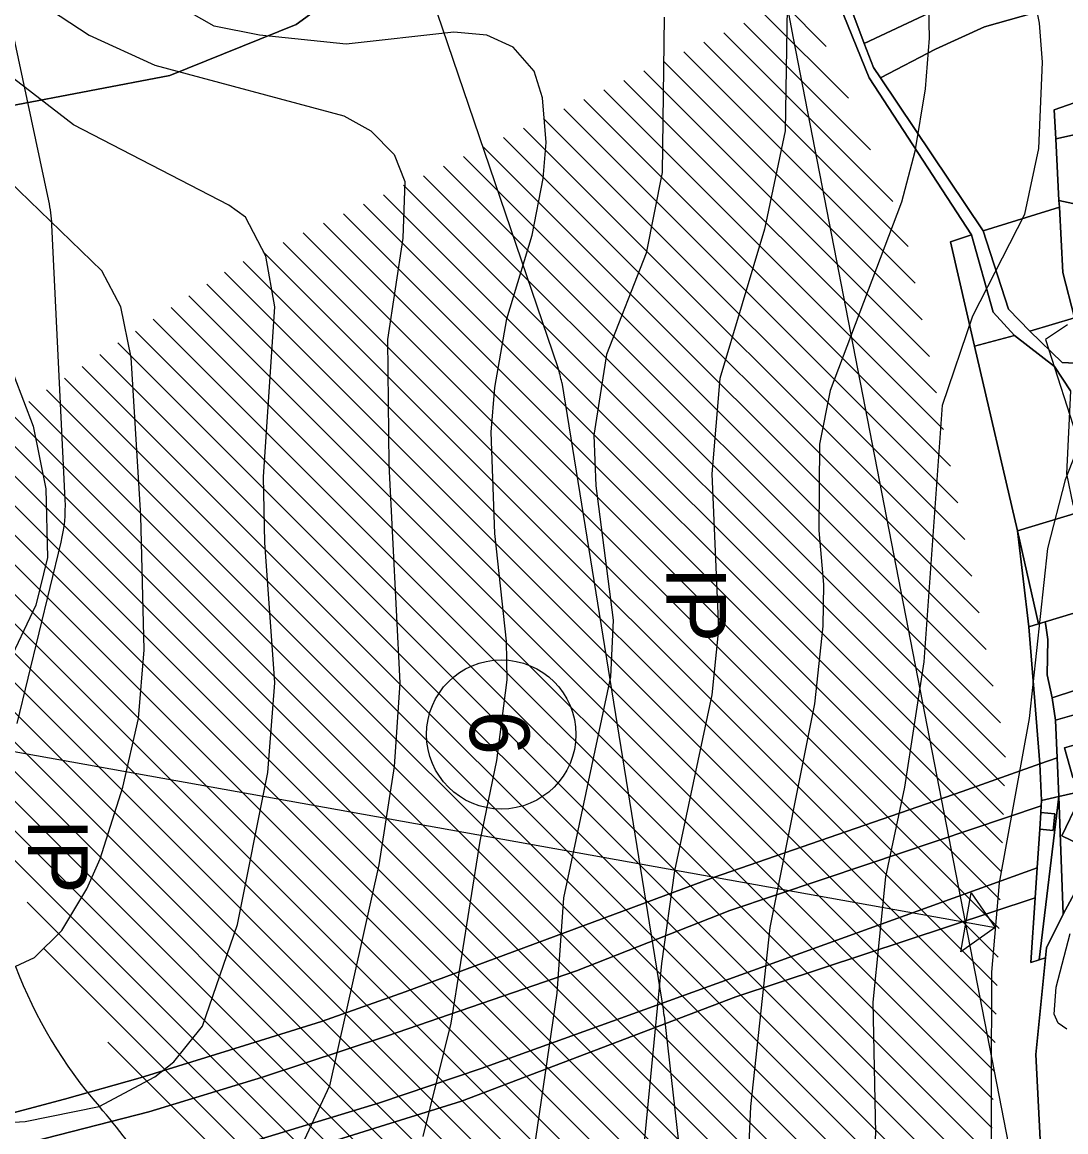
# Model space of a CAD drawing. Extents: x -510989 to -501240, y -1184665 to -1176098.
# Drawn here: x -509912.8 to -509563.3, y -1179809.4 to -1179437.6 of the extents above; entities that cross this region are included whole.
import ezdxf

# ---------------------------------------------------------------- set-up
doc = ezdxf.new("R2010")
doc.units = 0
for name, color, linetype in [('NAVRH_interakcni_prvky', 7, 'Continuous'), ('NAVRH_rozvodnice', 7, 'Continuous'), ('orna_puda', 7, 'Continuous'), ('ostatni_plocha_x_ostatni_komunikace', 7, 'Continuous'), ('ostatni_plocha_x_silnice', 7, 'Continuous'), ('ovocny_sad', 7, 'Continuous'), ('STAV_erozne_ohrozene_plochy', 7, 'Continuous'), ('STAV_odtokove_linie', 7, 'Continuous'), ('STAV_systematicke_odvodneni', 7, 'Continuous'), ('trvaly_travni_porost', 7, 'Continuous'), ('vrstevnice_01', 7, 'Continuous'), ('vrstevnice_02', 7, 'Continuous'), ('zahrada', 7, 'Continuous'), ('zastavena_plocha_a_nadvori', 7, 'Continuous')]:
    doc.layers.add(name, color=color, linetype=linetype)

msp = doc.modelspace()

# ---------------------------------------------------------------- linework, layer by layer
at = {"layer": 'NAVRH_interakcni_prvky'}
for p, q in [((-509791.67, -1179382.12), (-509733.43, -1179553.31)), ((-509903.92, -1179497.53), (-509919.26, -1179425.52)), ((-509898.44, -1179597.66), (-509902.88, -1179505.54)), ((-509732.15, -1179558.39), (-509698.04, -1179769.18)), ((-509914.54, -1179672.6), (-509899.79, -1179611.87)), ((-509697.84, -1179770.62), (-509679.58, -1179932.59))]:
    msp.add_line(p, q, dxfattribs=at)
for centre, start, end in [((-509952.82, -1179507.95), 2.7587, 12.0311), ((-509948.38, -1179600.07), 346.3496, 2.7587)]:
    msp.add_arc(centre, 50, start, end, dxfattribs=at)
for centre, start_param, end_param in [((-509813.59, -1179563.13), 0.096839, 0.201455), ((-509779.47, -1179773.93), 0.067567, 0.096839)]:
    msp.add_ellipse(centre, major_axis=(81.82, 0), ratio=0.600245, start_param=start_param, end_param=end_param, dxfattribs=at)
at = {"layer": 'NAVRH_rozvodnice'}
for centre, radius, start, end in [((-509769.66, -1179698.97), 155.49, 200.7272, 221.0092), ((-510050.65, -1179943.3), 216.87, 25.7756, 41.0092)]:
    msp.add_arc(centre, radius, start, end, dxfattribs=at)
at = {"layer": 'orna_puda'}
for points in [[(-509646.38, -1179413.87), (-509629.15, -1179456.33), (-509594.88, -1179508.89), (-509601.99, -1179511.21), (-509593.87, -1179546.25), (-509579.56, -1179608.03), (-509575.69, -1179640.23), (-509571.98, -1179686.17), (-509598.04, -1179695.37), (-509681.32, -1179724.23), (-509784.58, -1179762.55), (-509812.55, -1179772.46), (-509843.4, -1179782.08), (-509873.28, -1179791.41), (-509898.66, -1179798.48), (-509924.84, -1179805.39)], [(-510233.91, -1179517.72), (-510085.19, -1179504.1), (-510066.77, -1179500.85), (-510030.15, -1179490.83), (-510002.08, -1179487.1), (-509960.82, -1179477.55), (-509917.23, -1179465.75), (-509863.35, -1179455.49), (-509821.13, -1179438.42), (-509807.97, -1179428.77)], [(-509913.51, -1179813.75), (-509870.46, -1179802.75), (-509832.41, -1179791.08), (-509790.88, -1179777.39), (-509727.17, -1179755.55), (-509675.85, -1179735.34), (-509630, -1179719.89), (-509571.56, -1179700.19), (-509571.71, -1179702.48), (-509572.08, -1179708.08), (-509572.93, -1179721), (-509712.37, -1179771.32), (-509759.16, -1179788.2), (-509793.14, -1179799.75), (-509845.95, -1179815.81), (-509867.41, -1179823.72), (-509900.03, -1179832.04), (-509926.9, -1179837.49)], [(-509934.38, -1179847.85), (-509867.17, -1179830.91), (-509792.97, -1179807.66), (-509765.76, -1179799.13), (-509673.8, -1179764.23), (-509573.59, -1179731.06), (-509575.02, -1179752.72), (-509572.29, -1179751.86), (-509570.13, -1179751.18), (-509573.4, -1179783.55), (-509570.8, -1179833.9), (-509608.19, -1179847.61), (-509606.53, -1179883.25), (-509569.24, -1179868.59), (-509568.53, -1179892.94), (-509568.33, -1179899.97), (-509592.74, -1179908.1), (-509696.74, -1179942.74), (-509799.96, -1179976.4), (-509904.89, -1180011.19), (-509945.61, -1180021.74)]]:
    msp.add_lwpolyline(points, dxfattribs=at)
for points in [[(-509591.02, -1179507.59), (-509565.49, -1179499.64), (-509564.32, -1179521.49), (-509560.38, -1179536.66), (-509575.36, -1179541.18), (-509582.47, -1179533.78)], [(-509601.99, -1179511.21), (-509594.88, -1179508.89), (-509587.67, -1179534.77), (-509580.5, -1179542.59), (-509593.87, -1179546.25)], [(-509560.38, -1179536.66), (-509557.74, -1179545.16), (-509558.3, -1179552.05), (-509564.49, -1179551.71), (-509575.36, -1179541.18)], [(-509593.87, -1179546.25), (-509580.5, -1179542.59), (-509567.12, -1179553.04), (-509561.77, -1179561.13), (-509563.04, -1179588.93), (-509560.96, -1179599.22), (-509559.14, -1179601.9), (-509579.56, -1179608.03)], [(-509559.14, -1179601.9), (-509556.78, -1179605.36), (-509554.87, -1179614.83), (-509550.33, -1179622.85), (-509549.98, -1179627.33), (-509548.87, -1179632.92), (-509552.15, -1179633.05), (-509570.24, -1179638.57), (-509572.45, -1179639.24), (-509579.56, -1179608.03)], [(-509579.56, -1179608.03), (-509572.45, -1179639.24), (-509575.69, -1179640.23)], [(-509572.45, -1179639.24), (-509570.24, -1179638.57), (-509570.06, -1179639.82), (-509569.38, -1179644.52), (-509569.6, -1179656.29), (-509567.86, -1179664.07), (-509566.73, -1179671.5), (-509566.2, -1179684.13), (-509571.98, -1179686.17), (-509575.69, -1179640.23)], [(-509566.73, -1179671.5), (-509546.47, -1179665.67), (-509544.4, -1179672.71), (-509543.55, -1179692.05), (-509565.65, -1179697.05), (-509566.2, -1179684.13)], [(-509552.85, -1179677.69), (-509563.82, -1179680.81), (-509561.01, -1179690.71), (-509550.13, -1179687.62), (-509550.88, -1179685), (-509549.45, -1179684.59), (-509550.59, -1179680.57), (-509551.93, -1179680.95)], [(-509571.98, -1179686.17), (-509571.44, -1179698.45), (-509571.56, -1179700.19), (-509630, -1179719.89), (-509675.85, -1179735.34), (-509727.17, -1179755.55), (-509790.88, -1179777.39), (-509832.41, -1179791.08), (-509870.46, -1179802.75), (-509913.51, -1179813.75), (-509949.76, -1179823.34), (-509961.4, -1179812.45), (-509946.76, -1179810.17), (-509924.84, -1179805.39), (-509898.66, -1179798.48), (-509873.28, -1179791.41), (-509843.4, -1179782.08), (-509812.55, -1179772.46), (-509784.58, -1179762.55), (-509681.32, -1179724.23), (-509598.04, -1179695.37)], [(-509566.2, -1179684.13), (-509565.65, -1179697.05), (-509571.44, -1179698.45), (-509571.98, -1179686.17)], [(-509571.44, -1179698.45), (-509565.65, -1179697.05), (-509572.29, -1179751.86), (-509575.02, -1179752.72), (-509573.59, -1179731.06), (-509572.93, -1179721), (-509572.08, -1179708.08), (-509567.51, -1179708.49), (-509567.01, -1179702.9), (-509571.71, -1179702.48), (-509571.56, -1179700.19)], [(-509565.65, -1179697.05), (-509564.2, -1179736.53), (-509569.79, -1179747.85), (-509570.13, -1179751.18), (-509572.29, -1179751.86)], [(-509573.59, -1179731.06), (-509673.8, -1179764.23), (-509765.76, -1179799.13), (-509792.97, -1179807.66), (-509867.17, -1179830.91), (-509934.38, -1179847.85), (-509942.51, -1179849.9), (-509966.28, -1179853.46), (-510002.2, -1179858.21), (-510043.39, -1179861.58), (-510096.1, -1179867.95), (-510116.32, -1179858.81), (-510092.18, -1179857.59), (-509971.29, -1179844.16), (-509953.77, -1179842.93), (-509926.9, -1179837.49), (-509900.03, -1179832.04), (-509867.41, -1179823.72), (-509845.95, -1179815.81), (-509793.14, -1179799.75), (-509759.16, -1179788.2), (-509712.37, -1179771.32), (-509572.93, -1179721)]]:
    msp.add_lwpolyline(points, close=True, dxfattribs=at)
at = {"layer": 'ostatni_plocha_x_ostatni_komunikace'}
for points in [[(-509561.77, -1179561.13), (-509567.12, -1179553.04), (-509580.5, -1179542.59), (-509587.67, -1179534.77), (-509594.88, -1179508.89), (-509629.15, -1179456.33), (-509646.38, -1179413.87)], [(-509635.67, -1179431.97), (-509630.81, -1179444.75), (-509627.75, -1179452.82), (-509625.39, -1179456.34), (-509591.02, -1179507.59), (-509582.47, -1179533.78), (-509575.36, -1179541.18), (-509564.49, -1179551.71), (-509558.3, -1179552.05)]]:
    msp.add_lwpolyline(points, dxfattribs=at)
at = {"layer": 'ostatni_plocha_x_silnice'}
msp.add_lwpolyline([(-509563.62, -1180023.92), (-509565.24, -1180006.24), (-509567.68, -1179922.21), (-509567.84, -1179916.75), (-509568.18, -1179905.23), (-509568.33, -1179899.97), (-509568.53, -1179892.94), (-509569.24, -1179868.59), (-509570.8, -1179833.9), (-509573.4, -1179783.55), (-509570.13, -1179751.18), (-509569.79, -1179747.85), (-509564.2, -1179736.53), (-509552.3, -1179714.42)], dxfattribs=at)
at = {"layer": 'ovocny_sad'}
msp.add_lwpolyline([(-509558.04, -1179429.89), (-509547.82, -1179460.78), (-509551.94, -1179461.65), (-509567.22, -1179467.05), (-509566.71, -1179476.72), (-509565.61, -1179497.44), (-509565.49, -1179499.64), (-509591.02, -1179507.59), (-509625.39, -1179456.34), (-509607.01, -1179446.64), (-509590.53, -1179439.22)], close=True, dxfattribs=at)
at = {"layer": 'STAV_erozne_ohrozene_plochy'}
for p, q in [((-509657.7, -1179431.63), (-509643.57, -1179445.76)), ((-509664.41, -1179434.82), (-509636.14, -1179463.09)), ((-509671.12, -1179438.01), (-509628.71, -1179480.42)), ((-509684.54, -1179444.39), (-509616.15, -1179512.78)), ((-509677.83, -1179441.2), (-509621.28, -1179497.75)), ((-509691.24, -1179447.58), (-509613.77, -1179525.05)), ((-509697.95, -1179450.78), (-509611.4, -1179537.33)), ((-509704.66, -1179453.97), (-509609.02, -1179549.61)), ((-509711.37, -1179457.16), (-509606.64, -1179561.88)), ((-509718.07, -1179460.35), (-509604.27, -1179574.16)), ((-509731.49, -1179466.73), (-509599.51, -1179598.71)), ((-509724.78, -1179463.54), (-509601.89, -1179586.44)), ((-509738.2, -1179469.93), (-509597.13, -1179610.99)), ((-509744.91, -1179473.12), (-509594.76, -1179623.27)), ((-509751.61, -1179476.31), (-509592.38, -1179635.54)), ((-509758.32, -1179479.5), (-509590, -1179647.82)), ((-509765.03, -1179482.69), (-509587.63, -1179660.1)), ((-509778.44, -1179489.08), (-509583.56, -1179683.96)), ((-509771.74, -1179485.88), (-509585.25, -1179672.37)), ((-509785.15, -1179492.27), (-509583.9, -1179693.52)), ((-509791.86, -1179495.46), (-509584.24, -1179703.08)), ((-509798.57, -1179498.65), (-509584.58, -1179712.64)), ((-509805.28, -1179501.84), (-509584.92, -1179722.19)), ((-509811.98, -1179505.03), (-509585.26, -1179731.75)), ((-509825.4, -1179511.42), (-509585.94, -1179750.87)), ((-509818.69, -1179508.23), (-509585.6, -1179741.31)), ((-509832.11, -1179514.61), (-509586.29, -1179760.43)), ((-509838.82, -1179517.8), (-509586.63, -1179769.99)), ((-509845.08, -1179521.43), (-509586.97, -1179779.55)), ((-509851.04, -1179525.37), (-509587.31, -1179789.11)), ((-509857, -1179529.31), (-509587.65, -1179798.67)), ((-509862.96, -1179533.25), (-509587.99, -1179808.23)), ((-509868.92, -1179537.2), (-509588.33, -1179817.78)), ((-509874.88, -1179541.14), (-509588.67, -1179827.34)), ((-509880.83, -1179545.08), (-509589.01, -1179836.9)), ((-509886.79, -1179549.02), (-509589.35, -1179846.46)), ((-509892.75, -1179552.96), (-509589.69, -1179856.02)), ((-509898.71, -1179556.9), (-509590.03, -1179865.58)), ((-509904.67, -1179560.84), (-509590.37, -1179875.14)), ((-509910.63, -1179564.78), (-509590.71, -1179884.7)), ((-509916.58, -1179568.73), (-509591.05, -1179894.26)), ((-509922.54, -1179572.67), (-509596.68, -1179898.52)), ((-509928.5, -1179576.61), (-509607.05, -1179898.06)), ((-509934.46, -1179580.55), (-509617.42, -1179897.59)), ((-509937.21, -1179587.7), (-509627.79, -1179897.12)), ((-509937.11, -1179597.69), (-509638.15, -1179896.65)), ((-509937.02, -1179607.69), (-509648.52, -1179896.18)), ((-509936.93, -1179617.68), (-509658.89, -1179895.72)), ((-509936.83, -1179627.67), (-509669.26, -1179895.25)), ((-509936.74, -1179637.66), (-509679.62, -1179894.78)), ((-509936.65, -1179647.66), (-509689.99, -1179894.31)), ((-509936.54, -1179657.66), (-509700.36, -1179893.84)), ((-509931.47, -1179672.63), (-509710.73, -1179893.38)), ((-509926.4, -1179687.6), (-509721.09, -1179892.91)), ((-509921.33, -1179702.57), (-509731.46, -1179892.44)), ((-509916.26, -1179717.54), (-509741.83, -1179891.97)), ((-509911.19, -1179732.51), (-509752.2, -1179891.5)), ((-509905.49, -1179748.11), (-509762.56, -1179891.04)), ((-509884.12, -1179779.38), (-509772.93, -1179890.57))]:
    msp.add_line(p, q, dxfattribs=at)
at = {"layer": 'STAV_odtokove_linie'}
msp.add_line((-509940.81, -1179677.5), (-509586.94, -1179741), dxfattribs=at)
msp.add_lwpolyline([(-509595.03, -1179729.41), (-509586.94, -1179741), (-509598.53, -1179749.1)], close=True, dxfattribs=at)
msp.add_circle((-509752.4, -1179676.3), 25, dxfattribs=at)
at = {"layer": 'STAV_systematicke_odvodneni'}
for p, q in [((-509680.24, -1179309.07), (-509654.64, -1179442.96)), ((-509654.64, -1179442.96), (-509576.02, -1179847.16))]:
    msp.add_line(p, q, dxfattribs=at)
at = {"layer": 'trvaly_travni_porost'}
msp.add_lwpolyline([(-509807.97, -1179428.77), (-509821.13, -1179438.42), (-509863.35, -1179455.49), (-509917.23, -1179465.75), (-509960.82, -1179477.55), (-510002.08, -1179487.1), (-510030.15, -1179490.83), (-510066.77, -1179500.85), (-510085.19, -1179504.1), (-510233.91, -1179517.72)], dxfattribs=at)
at = {"layer": 'vrstevnice_01'}
for points in [[(-509609.91, -1179406), (-509609.09, -1179443), (-509610.41, -1179460), (-509613.91, -1179481), (-509618.31, -1179498), (-509642.19, -1179561), (-509645.81, -1179579), (-509646.09, -1179608), (-509644.5, -1179626), (-509644.69, -1179640), (-509647.5, -1179666), (-509662.5, -1179741), (-509668.91, -1179801), (-509670.09, -1179826)], [(-509919.19, -1179423), (-509890.41, -1179442), (-509868.41, -1179452)], [(-510068.54, -1179726.24), (-510055.19, -1179732), (-510040.69, -1179736), (-510006.09, -1179737), (-509990.69, -1179739), (-509976.09, -1179743), (-509947.81, -1179757), (-509934.31, -1179759), (-509921.5, -1179757), (-509908.69, -1179751), (-509899.59, -1179742), (-509891.19, -1179728), (-509886.69, -1179718), (-509879.09, -1179694), (-509873.91, -1179671), (-509872, -1179648), (-509873.09, -1179603), (-509876.31, -1179550), (-509879.81, -1179533), (-509886.19, -1179521), (-509934.69, -1179474), (-509963.31, -1179457), (-510012.09, -1179437)], [(-509697.81, -1179436), (-509698.5, -1179488), (-509703.81, -1179515), (-509717.19, -1179549), (-509721.41, -1179576), (-509720.69, -1179593), (-509714.91, -1179638), (-509715.81, -1179657), (-509731.5, -1179731), (-509733.81, -1179763), (-509742.31, -1179821), (-509749.19, -1179845), (-509758, -1179869), (-509773.59, -1179896), (-509786.69, -1179912), (-509801.09, -1179922), (-509818.91, -1179928), (-509840.81, -1179933), (-509855.91, -1179934), (-509880.19, -1179933), (-509901.19, -1179929), (-509930.69, -1179917)], [(-509868.41, -1179452), (-509805.09, -1179469), (-509796.09, -1179474), (-509788.31, -1179482), (-509784.69, -1179491), (-509785.41, -1179510), (-509790.5, -1179544), (-509790, -1179586), (-509786.31, -1179659), (-509788.31, -1179687), (-509793.41, -1179720), (-509809.91, -1179794), (-509820.59, -1179817), (-509829.69, -1179832), (-509846.81, -1179846), (-509863.91, -1179852), (-509881.09, -1179854), (-509900.59, -1179853), (-509918.5, -1179849)], [(-509562.81, -1179539), (-509570.09, -1179544), (-509558.81, -1179579), (-509563.5, -1179591), (-509569.5, -1179614), (-509575.59, -1179671), (-509585.69, -1179726), (-509588.19, -1179756), (-509588.41, -1179831), (-509590.81, -1179860), (-509596.91, -1179890), (-509609.41, -1179927), (-509618.91, -1179944), (-509631.69, -1179961), (-509658.91, -1179989), (-509692.91, -1180011), (-509699, -1180014), (-509709.31, -1180025)]]:
    msp.add_lwpolyline(points, dxfattribs=at)
at = {"layer": 'vrstevnice_02'}
for points in [[(-509765.91, -1180016), (-509747.09, -1180009), (-509720, -1179998), (-509704.5, -1179989), (-509690, -1179978), (-509677.5, -1179967), (-509663.91, -1179952), (-509653.81, -1179936), (-509646.5, -1179921), (-509637.91, -1179893), (-509630.59, -1179860), (-509627, -1179810), (-509627.81, -1179766), (-509623.59, -1179724), (-509617.19, -1179694), (-509610.81, -1179652), (-509604.59, -1179566), (-509594.5, -1179536), (-509577.09, -1179502), (-509572.41, -1179480), (-509571.09, -1179451), (-509572.19, -1179438), (-509578.81, -1179404)], [(-509656.31, -1179412), (-509657.31, -1179474), (-509664.19, -1179507), (-509679.19, -1179557), (-509681.91, -1179589), (-509679.59, -1179641), (-509681.91, -1179663), (-509694.41, -1179722), (-509698.69, -1179753), (-509706.09, -1179829), (-509718.69, -1179885), (-509732.69, -1179918), (-509749.81, -1179941), (-509768.91, -1179954), (-509790.41, -1179963), (-509809.81, -1179969), (-509824, -1179972), (-509852.81, -1179975), (-509877.41, -1179973), (-509892.19, -1179971), (-509919.41, -1179963)], [(-509778.59, -1179811), (-509769.19, -1179773), (-509759.41, -1179712), (-509753.91, -1179685), (-509750.41, -1179658), (-509750.69, -1179645), (-509754.59, -1179609), (-509755.81, -1179575), (-509754.59, -1179560), (-509750.5, -1179537), (-509742.09, -1179509), (-509738.31, -1179490), (-509737.31, -1179478), (-509738.59, -1179463), (-509741.41, -1179454), (-509748.41, -1179446), (-509757.19, -1179442), (-509768.31, -1179441), (-509804.31, -1179445), (-509833.41, -1179442), (-509848.59, -1179439), (-509865.81, -1179429)], [(-509928.81, -1179807), (-509911.81, -1179806), (-509887, -1179801), (-509868.41, -1179791), (-509862.09, -1179786), (-509852.5, -1179774), (-509840.69, -1179740), (-509830.59, -1179689), (-509828.19, -1179659), (-509831.59, -1179612), (-509832, -1179590), (-509828.19, -1179533), (-509831.19, -1179516), (-509838.09, -1179503), (-509843.59, -1179499), (-509895.69, -1179472), (-509932.09, -1179444)], [(-509915.59, -1179556), (-509909.19, -1179573), (-509904.91, -1179594), (-509904.31, -1179617), (-509908.31, -1179633), (-509918.19, -1179654)], [(-509563, -1179775), (-509565.91, -1179773), (-509567.19, -1179770), (-509566.5, -1179761), (-509561.91, -1179743)]]:
    msp.add_lwpolyline(points, dxfattribs=at)
at = {"layer": 'zahrada'}
for points in [[(-509601.16, -1179416.74), (-509573.56, -1179407.18), (-509569.19, -1179419.91), (-509592.83, -1179426.82), (-509630.81, -1179444.75), (-509635.67, -1179431.97)], [(-509569.19, -1179419.91), (-509567.48, -1179424.86), (-509558.37, -1179428.91), (-509558.04, -1179429.89), (-509590.53, -1179439.22), (-509607.01, -1179446.64), (-509625.39, -1179456.34), (-509627.75, -1179452.82), (-509630.81, -1179444.75), (-509592.83, -1179426.82)], [(-509547.82, -1179460.78), (-509546.58, -1179460.52), (-509543.29, -1179470.7), (-509530.37, -1179467.74), (-509531.87, -1179470.96), (-509532.92, -1179469.34), (-509545.43, -1179472.08), (-509550.38, -1179471.6), (-509550.53, -1179473.19), (-509566.71, -1179476.72), (-509567.22, -1179467.05), (-509551.94, -1179461.65)], [(-509531.87, -1179470.96), (-509536.77, -1179481.46), (-509541.27, -1179502.62), (-509565.61, -1179497.44), (-509566.71, -1179476.72), (-509550.53, -1179473.19), (-509551.6, -1179484.43), (-509541.39, -1179485.41), (-509540.16, -1179472.58), (-509545.43, -1179472.08), (-509532.92, -1179469.34)], [(-509565.49, -1179499.64), (-509565.61, -1179497.44), (-509541.27, -1179502.62), (-509538.89, -1179502.8), (-509543.27, -1179518.36), (-509560.38, -1179536.66), (-509564.32, -1179521.49)], [(-509544.22, -1179656.32), (-509543.32, -1179656.32), (-509545.12, -1179665.28), (-509546.47, -1179665.67), (-509566.73, -1179671.5), (-509567.86, -1179664.07), (-509551.88, -1179658.83)], [(-509543.55, -1179692.05), (-509538.63, -1179690.94), (-509540.67, -1179698.57), (-509552.3, -1179714.42), (-509564.2, -1179736.53), (-509565.65, -1179697.05)], [(-509549.63, -1179703.45), (-509559.23, -1179698.87), (-509564.7, -1179710.32), (-509556.09, -1179714.43), (-509553.37, -1179708.74), (-509552.38, -1179709.22)]]:
    msp.add_lwpolyline(points, close=True, dxfattribs=at)
at = {"layer": 'zastavena_plocha_a_nadvori'}
for points in [[(-509552.15, -1179633.05), (-509548.87, -1179632.92), (-509548.34, -1179635.59), (-509547.39, -1179640.4), (-509546.58, -1179644.47), (-509545.06, -1179652.13), (-509544.22, -1179656.32), (-509551.88, -1179658.83), (-509567.86, -1179664.07), (-509569.6, -1179656.29), (-509569.38, -1179644.52), (-509570.06, -1179639.82), (-509570.24, -1179638.57)], [(-509552.85, -1179677.69), (-509551.93, -1179680.95), (-509550.59, -1179680.57), (-509549.45, -1179684.59), (-509550.88, -1179685), (-509550.13, -1179687.62), (-509561.01, -1179690.71), (-509563.82, -1179680.81)], [(-509549.63, -1179703.45), (-509552.38, -1179709.22), (-509553.37, -1179708.74), (-509556.09, -1179714.43), (-509564.7, -1179710.32), (-509559.23, -1179698.87)], [(-509571.71, -1179702.48), (-509567.01, -1179702.9), (-509567.51, -1179708.49), (-509572.08, -1179708.08)]]:
    msp.add_lwpolyline(points, close=True, dxfattribs=at)

# ---------------------------------------------------------------- texts
at = {"layer": 'NAVRH_interakcni_prvky'}
for p in [(-509697.12, -1179620.12), (-509910.9, -1179704.35)]:
    msp.add_text('IP', height=20, rotation=270, dxfattribs=at).set_placement(p)
at = {"layer": 'STAV_odtokove_linie'}
msp.add_text('6', height=20, rotation=270, dxfattribs=at).set_placement((-509762.94, -1179668.27))

doc.saveas('drawing.dxf')
